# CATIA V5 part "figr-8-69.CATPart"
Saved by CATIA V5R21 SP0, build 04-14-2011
Part number: Part1
Bounding box of the stored display mesh (mm): x -75 to 75, y -65.851 to 65.851, z 0 to 50
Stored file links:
  D:\CATIA V5R21 E-RESOURCES\CATIA-V5R21\catia-v5r21-prt\c08-catia-v5r20-prt\c08-catia-v5r21-figr-8-69.CATPart
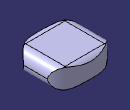
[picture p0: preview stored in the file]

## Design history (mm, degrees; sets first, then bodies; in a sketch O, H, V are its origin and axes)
Body1 (main body)
  Sketch1 on xy-plane, origin (0, 0, 0), H (1, 0, 0), V (0, 1, 0)
    line L1 (-75, 75) -> (75, 75)
    line L2 (75, 75) -> (75, -75)
    line L3 (75, -75) -> (-75, -75)
    line L4 (-75, -75) -> (-75, 75)
    axis line L5 (75, -75) -> (-75, 75)
    length L3 = 150
    length L2 = 150
    horizontal: L1 H, L3 H
    vertical: L2 V, L4 V
    midpoint: O L5
  Pad1: profile Sketch1, direction (0, 0, 1), length 50
  Fillet1: radius 25, on face of Pad1 (x6)
  Body2
    Sketch2 on xy-plane, origin (0, 0, 0), H (1, 0, 0), V (0, 1, 0)
      ellipse A1 centre (0, 0) semi-axes 84.7617, 65.8627 rotation 0
      point P1 (84.7617, 0)
      point P2 (0, 65.8627)
      coincidence: P1 H, P2 V, A1 P1, A1 P2
    Pad2: profile Sketch2, direction (0, 0, 1), length 50
  Intersect1: tool Body2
